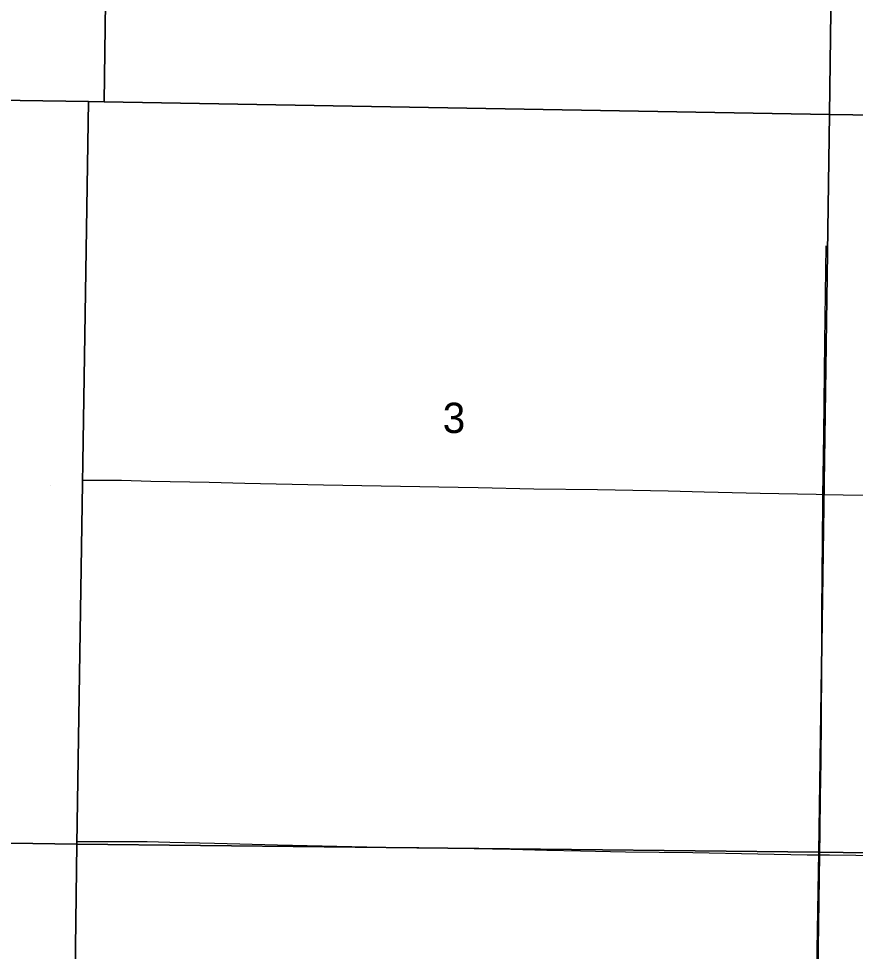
# Model space of a CAD drawing. Extents: x 1587405 to 1714697, y 1028970 to 1155083.
# Drawn here: x 1634826 to 1640942, y 1118281 to 1125096 of the extents above; entities that cross this region are included whole.
import ezdxf

# ---------------------------------------------------------------- set-up
doc = ezdxf.new("R2010")
doc.units = 0
for name, color, linetype in [('GM_X_County_Road', 7, 'Continuous'), ('GM_X_Section', 7, 'Continuous'), ('GM_X_Section_Text', 7, 'Continuous'), ('GM_X_Township_Road', 7, 'Continuous'), ('GM_X_Unincorporated_Location', 7, 'Continuous')]:
    doc.layers.add(name, color=color, linetype=linetype)

msp = doc.modelspace()

# ---------------------------------------------------------------- linework, layer by layer
at = {"layer": 'GM_X_County_Road'}
for points in [[(1640704.7, 1121619.6), (1640707, 1121751), (1640710.6, 1122062.7), (1640719.5, 1122735.4), (1640729.7, 1123435.4)], [(1640682.4, 1118986.7), (1640684.5, 1119158.6), (1640688.5, 1119404.7), (1640691.6, 1119667.1), (1640693.5, 1119979), (1640696, 1120356.3), (1640697.4, 1120766.6), (1640703.5, 1121554.2), (1640704.7, 1121619.6)], [(1640704.7, 1121619.6), (1640853.1, 1121617.5), (1641049.9, 1121614.8), (1641246.9, 1121613.5), (1641509.3, 1121609.7), (1641765.5, 1121606.8)], [(1640664.6, 1117608.3), (1640673.7, 1118305.5), (1640682.4, 1118986.7)]]:
    msp.add_lwpolyline(points, dxfattribs=at)
at = {"layer": 'GM_X_Section'}
for points in [[(1630216.9, 1129877.3), (1635520.8, 1129774), (1635451.6, 1124487.6), (1635335.6, 1124489.2), (1630175.4, 1124564.7)], [(1635520.8, 1129774), (1640820.7, 1129674.6), (1640753.6, 1124394.2), (1635451.6, 1124487.6)], [(1640820.7, 1129674.6), (1646147.1, 1129602.9), (1646073.9, 1124318.5), (1646049.9, 1124318.8), (1640753.6, 1124394.2)], [(1630175.4, 1124564.7), (1635335.6, 1124489.2), (1635250.6, 1119065), (1629922.5, 1119144.8), (1630031.5, 1124568.6)], [(1635451.6, 1124487.6), (1640753.6, 1124394.2), (1640675, 1119006), (1635250.6, 1119065), (1635335.6, 1124489.2)], [(1646049.9, 1124318.8), (1645977.3, 1118932.5), (1640675, 1119006), (1640753.6, 1124394.2)], [(1629922.5, 1119144.8), (1635250.6, 1119065), (1635183.5, 1113790.7), (1629851.3, 1113866.6)], [(1635250.6, 1119065), (1640675, 1119006), (1640585.8, 1113725.9), (1635183.5, 1113790.7)], [(1640675, 1119006), (1645977.3, 1118932.5), (1645830.1, 1113663.1), (1640585.8, 1113725.9)]]:
    msp.add_lwpolyline(points, close=True, dxfattribs=at)
at = {"layer": 'GM_X_Township_Road'}
for points in [[(1635291.8, 1121724.7), (1635464, 1121724.5), (1635578.8, 1121722.3), (1635791.9, 1121716.4), (1636218.2, 1121708.9), (1636480.4, 1121700.4), (1637054.4, 1121689.7), (1638038.4, 1121672.2), (1638186.1, 1121669.9), (1638592.7, 1121661), (1639057.2, 1121654.3), (1639574.4, 1121644.6), (1639836.7, 1121637.5), (1640246.6, 1121627.4), (1640656.6, 1121620.4), (1640704.7, 1121619.6)], [(1635253.8, 1119083.5), (1635290.6, 1119083.5), (1635766.3, 1119082.4), (1635930.4, 1119079.1), (1636258.5, 1119072.2), (1636717.7, 1119058.9), (1637587.2, 1119040.5), (1637751.4, 1119038.4), (1638424.1, 1119027.8), (1638686.6, 1119020.2), (1638932.7, 1119016.2), (1639260.9, 1119009), (1639753.2, 1119002.9), (1640229, 1118993.4), (1640590, 1118986.4), (1640682.4, 1118986.7)], [(1640682.4, 1118986.7), (1640754, 1118987), (1641328.2, 1118978.5), (1642083.1, 1118972.6), (1642345.5, 1118967.6), (1642918.8, 1118960.5), (1643197.8, 1118957.4), (1643476.8, 1118952), (1644166, 1118942.2), (1644403.1, 1118939), (1644738.8, 1118933)]]:
    msp.add_lwpolyline(points, dxfattribs=at)
at = {"layer": 'GM_X_Unincorporated_Location'}
msp.add_line((1635059.7, 1121681.9), (1635059.7, 1121681.9), dxfattribs=at)

# ---------------------------------------------------------------- texts
at = {"layer": 'GM_X_Section_Text'}
msp.add_text('3', height=221, rotation=0.00001, dxfattribs=at).set_placement((1637926.2, 1122068.2))

doc.saveas('drawing.dxf')
